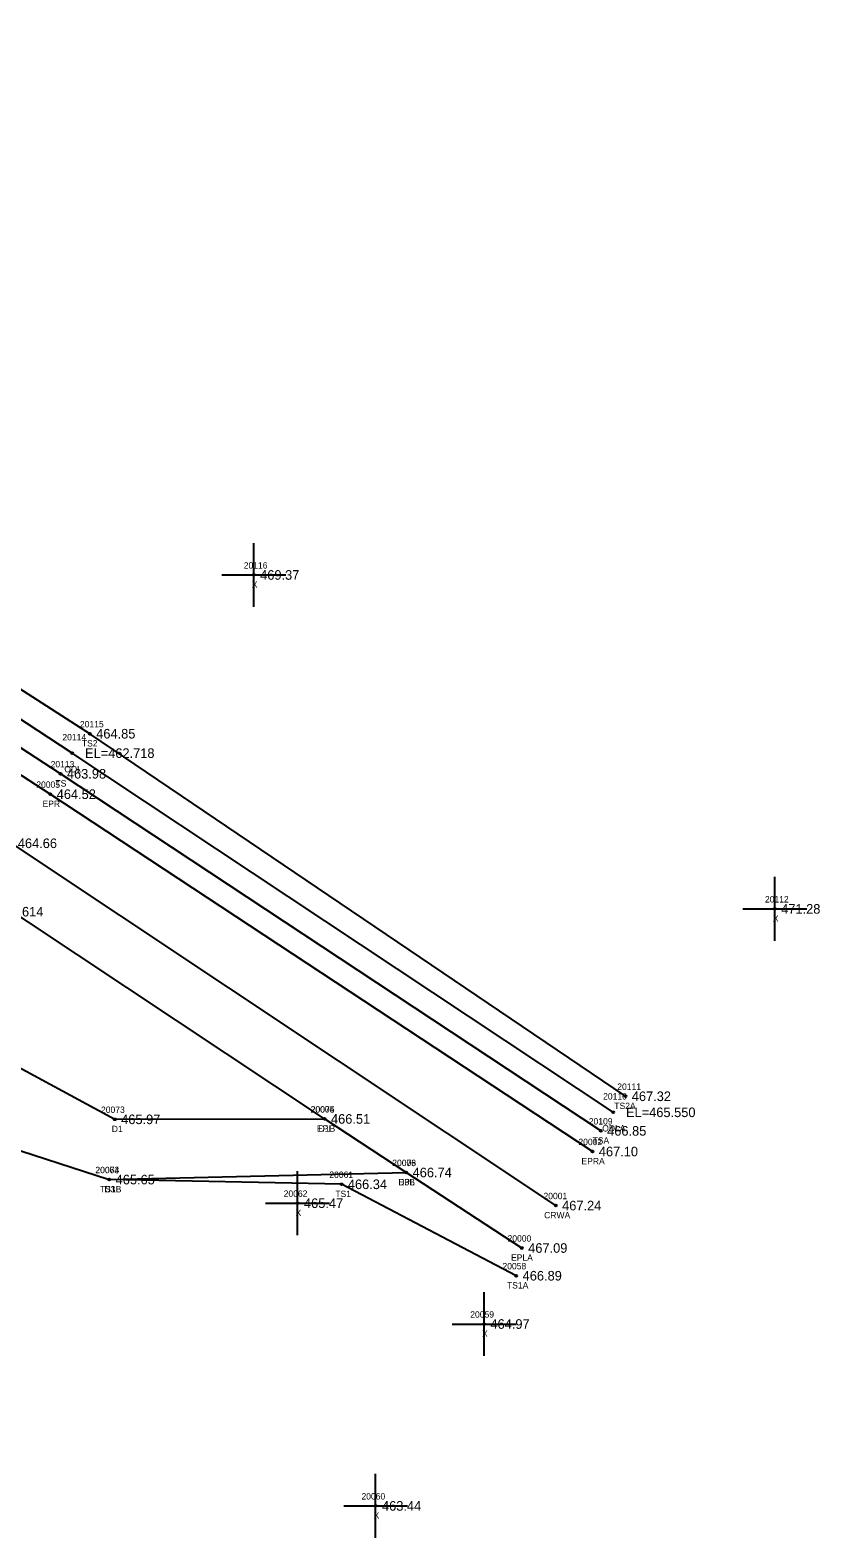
# Model space of a CAD drawing. Extents: x 1797709 to 1799052, y 896018 to 896955.
# Drawn here: x 1798928.8 to 1799052.4, y 896017.9 to 896253.9 of the extents above; entities that cross this region are included whole.
import ezdxf

# ---------------------------------------------------------------- set-up
doc = ezdxf.new("R2010")
doc.units = 0
for name, color, linetype in [('RD_DTM_BkLn1', 7, 'Continuous'), ('RD_DTM_BkLn2', 7, 'Continuous'), ('RD_DTM_BkLn_txCode', 7, 'Continuous'), ('RD_EX_Driveway', 7, 'Continuous'), ('RD_EX_Driveway_txCode', 7, 'Continuous'), ('RD_EX_H2O', 7, 'Continuous'), ('RD_EX_H2O_txCode', 7, 'Continuous'), ('RD_EX_Misc', 7, 'Continuous'), ('RD_EX_Misc_txCode', 7, 'Continuous'), ('RD_EX_Road', 7, 'Continuous'), ('RD_EX_Road_txCode', 7, 'Continuous'), ('RD_EX_TX_Driveway_ELEV', 7, 'Continuous'), ('RD_EX_TX_H2O_ELEV', 7, 'Continuous'), ('RD_EX_TX_Misc_ELEV', 7, 'Continuous'), ('RD_EX_TX_Road_ELEV', 7, 'Continuous'), ('RD_HC_Survey_ELEV', 7, 'Continuous'), ('RD_HC_Survey_txCode', 7, 'Continuous'), ('RD_SMD_Locator', 7, 'Continuous')]:
    doc.layers.add(name, color=color, linetype=linetype)

msp = doc.modelspace()

# ---------------------------------------------------------------- linework, layer by layer
at = {"layer": 'RD_DTM_BkLn1'}
msp.add_lwpolyline([(1799011.08, 896069.91), (1798925.85, 896126.62), (1798837.59, 896184.3), (1798748.15, 896241.48), (1798659.28, 896299.6), (1798569.04, 896359.56), (1798481.49, 896418.06), (1798400.67, 896472.53)], dxfattribs=at)
at = {"layer": 'RD_DTM_BkLn2'}
for points in [[(1799018.13, 896081.6), (1798933.54, 896137.5), (1798843.36, 896196.36), (1798754.6, 896254.77), (1798666.48, 896312.08), (1798576.97, 896371.21), (1798490.12, 896433.01), (1798431.99, 896471.79), (1798411.1, 896485.73), (1798407.22, 896483.62)], [(1799021.99, 896087.02), (1798938.13, 896143.77), (1798847.7, 896201.86), (1798779.67, 896245.03)], [(1799004.9, 896058.93), (1798977.53, 896073.24), (1798941.17, 896073.98)]]:
    msp.add_lwpolyline(points, dxfattribs=at)
at = {"layer": 'RD_EX_Driveway'}
for points in [[(1798822.63, 896182.83), (1798817.4, 896170.97), (1798816.49, 896153.9), (1798843.32, 896121.14), (1798905.58, 896085.5), (1798941.17, 896073.98), (1798987.67, 896075.09)], [(1798834.47, 896175.11), (1798828.77, 896166.14), (1798829.23, 896153.73), (1798849.01, 896132), (1798909.77, 896100.86), (1798942.04, 896083.41), (1798974.89, 896083.47)]]:
    msp.add_lwpolyline(points, dxfattribs=at)
at = {"layer": 'RD_EX_H2O'}
msp.add_lwpolyline([(1799020.09, 896084.51), (1798935.38, 896140.73), (1798845.54, 896199.69), (1798779.67, 896245.03)], dxfattribs=at)
at = {"layer": 'RD_EX_Misc'}
for p, q in [((1798963.8, 896163.62), (1798963.8, 896173.62)), ((1798958.8, 896168.62), (1798968.8, 896168.62)), ((1799045.39, 896111.35), (1799045.39, 896121.35)), ((1799040.39, 896116.35), (1799050.39, 896116.35)), ((1798970.66, 896065.28), (1798970.66, 896075.28)), ((1798965.66, 896070.28), (1798975.66, 896070.28)), ((1798999.86, 896046.37), (1798999.86, 896056.37)), ((1798994.86, 896051.37), (1799004.86, 896051.37)), ((1798982.88, 896017.9), (1798982.88, 896027.9)), ((1798977.88, 896022.9), (1798987.88, 896022.9))]:
    msp.add_line(p, q, dxfattribs=at)
at = {"layer": 'RD_EX_Road'}
for points in [[(1799016.83, 896078.37), (1798931.94, 896134.3), (1798843.73, 896191.67), (1798753.3, 896249.87), (1798664.51, 896307.9), (1798573.47, 896367.69), (1798486.82, 896425.22), (1798405.79, 896479.79), (1798400.67, 896472.53)], [(1799005.77, 896063.27), (1798987.67, 896075.09), (1798974.89, 896083.47), (1798920.67, 896119.42), (1798834.47, 896175.11), (1798832.16, 896176.64), (1798822.63, 896182.83), (1798742.86, 896234.39), (1798653.4, 896292.37), (1798563.64, 896351.71), (1798476.02, 896410.61), (1798395.49, 896463.92), (1798400.67, 896472.53)]]:
    msp.add_lwpolyline(points, dxfattribs=at)
at = {"layer": 'RD_SMD_Locator'}
for centre in [(1798963.8, 896168.62), (1798938.13, 896143.77), (1798935.38, 896140.73), (1798933.54, 896137.5), (1798931.94, 896134.3), (1799045.39, 896116.35), (1799021.99, 896087.02), (1799020.09, 896084.51), (1798942.04, 896083.41), (1798974.89, 896083.47), (1798974.89, 896083.47), (1799018.13, 896081.6), (1799016.83, 896078.37), (1798987.67, 896075.09), (1798987.67, 896075.09), (1798941.17, 896073.98), (1798941.17, 896073.98), (1798977.53, 896073.24), (1798970.66, 896070.28), (1799011.08, 896069.91), (1799005.77, 896063.27), (1799004.9, 896058.93), (1798999.86, 896051.37), (1798982.88, 896022.9)]:
    msp.add_circle(centre, 0.15, dxfattribs=at)

# ---------------------------------------------------------------- texts
at = {"layer": 'RD_DTM_BkLn_txCode'}
for s, p in [('20115', (1798936.58, 896144.77)), ('TS2', (1798936.88, 896141.77)), ('20113', (1798931.99, 896138.5)), ('TS', (1798932.74, 896135.5)), ('20111', (1799020.72, 896088.02)), ('TS2A', (1799020.25, 896085.02)), ('20109', (1799016.26, 896082.6)), ('TSA', (1799016.85, 896079.6)), ('20063', (1798938.99, 896074.98)), ('20061', (1798975.63, 896074.24)), ('TS1B', (1798939.73, 896071.98)), ('TS1', (1798976.57, 896071.24)), ('20058', (1799002.74, 896059.93)), ('TS1A', (1799003.45, 896056.93))]:
    msp.add_text(s, height=1, dxfattribs=at).set_placement(p)
at = {"layer": 'RD_EX_Driveway_txCode'}
for s, p in [('20073', (1798939.88, 896084.41)), ('20075', (1798972.73, 896084.47)), ('D1', (1798941.56, 896081.41)), ('D1B', (1798973.95, 896081.47)), ('20076', (1798985.49, 896076.09)), ('20074', (1798939.01, 896074.98)), ('D3', (1798940.41, 896071.98)), ('D3B', (1798986.44, 896073.09))]:
    msp.add_text(s, height=1, dxfattribs=at).set_placement(p)
at = {"layer": 'RD_EX_H2O_txCode'}
for s, p in [('20114', (1798933.83, 896142.73)), ('ODL', (1798934.13, 896137.73)), ('20110', (1799018.5, 896086.51)), ('ODLA', (1799018.36, 896081.51))]:
    msp.add_text(s, height=1, dxfattribs=at).set_placement(p)
at = {"layer": 'RD_EX_Misc_txCode'}
for s, p in [('20116', (1798962.23, 896169.62)), ('X', (1798963.49, 896166.62)), ('20112', (1799043.84, 896117.35)), ('X', (1799045.08, 896114.35)), ('20062', (1798968.48, 896071.28)), ('X', (1798970.34, 896068.28)), ('20059', (1798997.7, 896052.37)), ('X', (1798999.54, 896049.37)), ('20060', (1798980.66, 896023.9)), ('X', (1798982.56, 896020.9))]:
    msp.add_text(s, height=1, dxfattribs=at).set_placement(p)
at = {"layer": 'RD_EX_Road_txCode'}
for s, p in [('20005', (1798929.75, 896135.3)), ('EPR', (1798930.72, 896132.3)), ('20004', (1798972.69, 896084.47)), ('EPL', (1798973.69, 896081.47)), ('20002', (1799014.63, 896079.37)), ('20003', (1798985.48, 896076.09)), ('EPRA', (1799015.11, 896076.37)), ('EPL', (1798986.47, 896073.09)), ('20000', (1799003.54, 896064.27)), ('EPLA', (1799004.08, 896061.27))]:
    msp.add_text(s, height=1, dxfattribs=at).set_placement(p)
at = {"layer": 'RD_EX_TX_Driveway_ELEV'}
for s, p in [('465.97', (1798943.04, 896082.66)), ('466.51', (1798975.89, 896082.72)), ('465.65', (1798942.17, 896073.23)), ('466.74', (1798988.67, 896074.34))]:
    msp.add_text(s, height=1.5, dxfattribs=at).set_placement(p)
at = {"layer": 'RD_EX_TX_H2O_ELEV'}
for s, p in [('EL=462.718', (1798937.38, 896139.98)), ('EL=464.614', (1798919.98, 896115.16)), ('EL=465.550', (1799022.09, 896083.76))]:
    msp.add_text(s, height=1.5, dxfattribs=at).set_placement(p)
at = {"layer": 'RD_EX_TX_Misc_ELEV'}
for s, p in [('469.37', (1798964.8, 896167.87)), ('464.85', (1798939.13, 896143.02)), ('463.98', (1798934.54, 896136.75)), ('471.28', (1799046.39, 896115.6)), ('467.32', (1799022.99, 896086.27)), ('466.85', (1799019.13, 896080.85)), ('465.65', (1798942.17, 896073.23)), ('466.34', (1798978.53, 896072.49)), ('465.47', (1798971.66, 896069.53)), ('466.89', (1799005.9, 896058.18)), ('464.97', (1799000.86, 896050.62)), ('463.44', (1798983.88, 896022.15))]:
    msp.add_text(s, height=1.5, dxfattribs=at).set_placement(p)
at = {"layer": 'RD_EX_TX_Road_ELEV'}
for s, p in [('464.52', (1798932.94, 896133.55)), ('466.51', (1798975.89, 896082.72)), ('467.10', (1799017.83, 896077.62)), ('466.74', (1798988.67, 896074.34)), ('467.09', (1799006.77, 896062.52))]:
    msp.add_text(s, height=1.5, dxfattribs=at).set_placement(p)
at = {"layer": 'RD_HC_Survey_ELEV'}
for s, p in [('464.66', (1798926.85, 896125.87)), ('467.24', (1799012.08, 896069.16))]:
    msp.add_text(s, height=1.5, dxfattribs=at).set_placement(p)
at = {"layer": 'RD_HC_Survey_txCode'}
for s, p in [('20001', (1799009.16, 896070.91)), ('CRWA', (1799009.27, 896067.91))]:
    msp.add_text(s, height=1, dxfattribs=at).set_placement(p)

doc.saveas('drawing.dxf')
